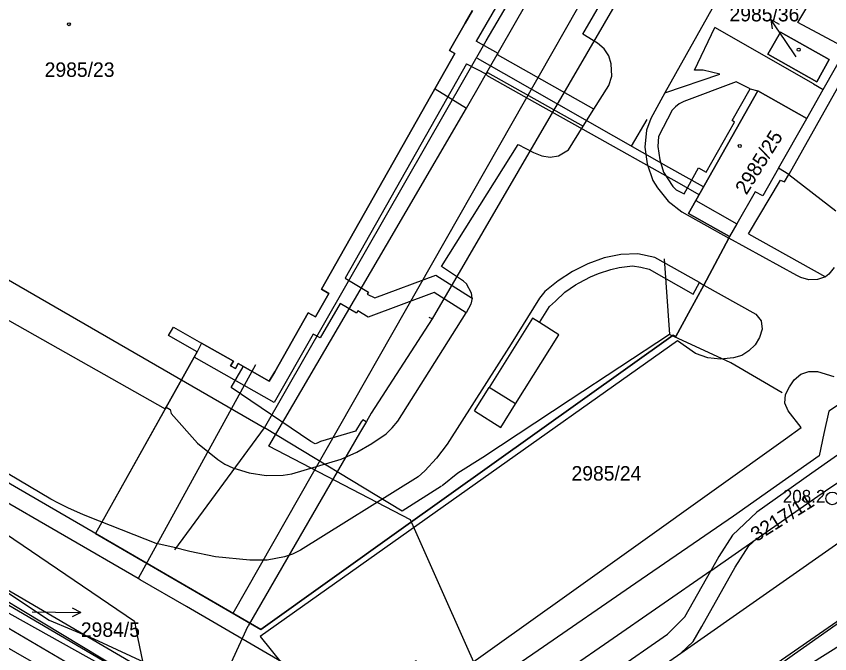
# Model space of a CAD drawing. Extents: x -620475 to -619963, y -1123010 to -1122510.
# Drawn here: x -620108.2 to -620012.5, y -1122830.6 to -1122755.5 of the extents above; entities that cross this region are included whole.
import ezdxf

# ---------------------------------------------------------------- set-up
doc = ezdxf.new("R2010")
doc.units = 0
for name, color, linetype in [('CETIN', 7, 'Continuous'), ('GasNet', 7, 'Continuous'), ('Hranice parcel', 7, 'Continuous'), ('Parcelní čísla', 7, 'Continuous'), ('Pop  PČ popisy', 7, 'Continuous'), ('VAS stoka', 7, 'Continuous'), ('VAS vodovod', 7, 'Continuous'), ('Vnitřní kresba', 7, 'Continuous'), ('Věcná břemena k části', 7, 'Continuous'), ('Značky bodu BP', 7, 'Continuous'), ('Značky budov', 7, 'Continuous')]:
    doc.layers.add(name, color=color, linetype=linetype)

msp = doc.modelspace()

# ---------------------------------------------------------------- linework, layer by layer
at = {"layer": 'CETIN'}
for points in [[(-620322.39, -1122622.262), (-620301.06, -1122636.75), (-620273.539, -1122652.218), (-620253.246, -1122663.163), (-620204.022, -1122698.845), (-620159.643, -1122769.192), (-620144.669, -1122791.286), (-620140.333, -1122798.335), (-620134.98, -1122805.248), (-620121.226, -1122817.175), (-620095.953, -1122832.424), (-620068.004, -1122848.181)], [(-620164.261, -1122757.63), (-620162.95, -1122761.03), (-620156.11, -1122769.9), (-620136.563, -1122796.46), (-620117.888, -1122817.631), (-620104.34, -1122826.6), (-620099.09, -1122828.81), (-620092.09, -1122832.08), (-620086.33, -1122833.54), (-620081.024, -1122834.312)]]:
    msp.add_lwpolyline(points, dxfattribs=at)
at = {"layer": 'GasNet'}
for points in [[(-620046.14, -1122851.29), (-620053.62, -1122841.38), (-620061.16, -1122831.41), (-620068.48, -1122836.5), (-620088.2, -1122824.99), (-620093.656, -1122821.845), (-620093.89, -1122821.71), (-620111.26, -1122811.68), (-620133.38, -1122798.37), (-620145.72, -1122781.6), (-620162.54, -1122758.52), (-620166.304, -1122761.04), (-620166.886, -1122761.429), (-620167.468, -1122761.818), (-620169.13, -1122762.93), (-620169.189, -1122762.97)], [(-620080.07, -1122796.57), (-620093.89, -1122821.71)], [(-619978.453, -1122804.325), (-619997.91, -1122817.46), (-620001.69, -1122820.05), (-620016.67, -1122830.62), (-620025.79, -1122837.14), (-620030.05, -1122839.94), (-620046.14, -1122851.29)]]:
    msp.add_lwpolyline(points, dxfattribs=at)
at = {"layer": 'Hranice parcel'}
for p, q in [((-620018.54, -1122773.42), (-620015.21, -1122767.58)), ((-620026.52, -1122820.79), (-620021.18, -1122817.07))]:
    msp.add_line(p, q, dxfattribs=at)
for points in [[(-620027.34, -1122787.19), (-620029.12, -1122790.47), (-620030.63, -1122793.23), (-620030.93, -1122793.08), (-620062.93, -1122815.9), (-620079.47, -1122827.69), (-620107.97, -1122811.15), (-620126.88, -1122800.18), (-620134.93, -1122794.41), (-620148.77, -1122775.1), (-620158.3, -1122761.8), (-620160.13, -1122754.62), (-620158.82, -1122744.94), (-620155.87, -1122738.11), (-620144.37, -1122714.62)], [(-620004.122, -1122750.583), (-620017.33, -1122774.17), (-620018.54, -1122773.42)], [(-620015.21, -1122767.58), (-620013.28, -1122764.14), (-620010.56, -1122759.32), (-620016.25, -1122756.27), (-620012.77, -1122750.41)], [(-620122.58, -1122783.75), (-620090.7, -1122801.75), (-620090.59, -1122801.55), (-620087.3, -1122795.66), (-620086.96, -1122795.04), (-620090.3, -1122793.12), (-620089.73, -1122792.12), (-620086.43, -1122793.99), (-620082.68, -1122796.11), (-620083.01, -1122796.68), (-620082.45, -1122797), (-620082.12, -1122796.42), (-620078.46, -1122798.5), (-620077.82, -1122797.38), (-620073.87, -1122790.42), (-620073.02, -1122790.9), (-620071.46, -1122788.15), (-620072.31, -1122787.67), (-620056.64, -1122759.92), (-620057.24, -1122759.58), (-620055.41, -1122756.34), (-620054.56, -1122754.84)], [(-620019.78, -1122760.01), (-620014.04, -1122763.25), (-620012.58, -1122760.64), (-620018.31, -1122757.41), (-620019.78, -1122760.01)], [(-620072.47, -1122846.25), (-620119.48, -1122820.03), (-620130.17, -1122810.08), (-620136, -1122804.68), (-620136.79, -1122803.52), (-620163.81, -1122763.48)], [(-620069.79, -1122845.77), (-620093.24, -1122832.45), (-620114.36, -1122820.1), (-620123.37, -1122813.77), (-620129.15, -1122808.98), (-620134.98, -1122803.58), (-620147.22, -1122786.5), (-620163.81, -1122763.48)], [(-620015.21, -1122767.58), (-620020.97, -1122764.3), (-620028.26, -1122777.23), (-620029.12, -1122778.75), (-620024.29, -1122781.46)], [(-620074.02, -1122848.16), (-620095.17, -1122835.78), (-620116.57, -1122823.25), (-620125.58, -1122816.92), (-620133.3, -1122810.53), (-620139.43, -1122803.84), (-620150.35, -1122788.75), (-620165.02, -1122768.39), (-620166.09, -1122767.67), (-620166.7, -1122767.69)], [(-620018.54, -1122773.42), (-620020.4, -1122776.68), (-620021.28, -1122776.18), (-620023.43, -1122779.95), (-620024.29, -1122781.46)], [(-620024.29, -1122781.46), (-620024.38, -1122781.64), (-620027.34, -1122787.19)], [(-620027.34, -1122787.19), (-620021.21, -1122790.6), (-620020.57, -1122791.37), (-620020.47, -1122792.38), (-620020.76, -1122793.34), (-620021.28, -1122794.22), (-620022.02, -1122794.92), (-620022.87, -1122795.46), (-620023.84, -1122795.75), (-620024.96, -1122795.87), (-620025.37, -1122795.91), (-620026.87, -1122795.75), (-620028.3, -1122795.22), (-620030.44, -1122793.73), (-620056.1, -1122811.95), (-620079.53, -1122828.52), (-620068.86, -1122841.8), (-620043.43, -1122823.66), (-620017.73, -1122805.26), (-620015.89, -1122803.95), (-620017.39, -1122801.99), (-620017.8, -1122801.06), (-620017.7, -1122800.06), (-620017.25, -1122799.14), (-620016.69, -1122798.31), (-620015.92, -1122797.65), (-620014.98, -1122797.35), (-620013.97, -1122797.33), (-620012.05, -1122797.95)], [(-619977.351, -1122803.065), (-619989.26, -1122811.36), (-619995.85, -1122815.89), (-620011.68, -1122826.8), (-620019.22, -1122832.01), (-620044.54, -1122849.47), (-620064.79, -1122863.44), (-620079.86, -1122873.87), (-620081.95, -1122879.05), (-620081.71, -1122879.39)], [(-620007.52, -1122804.34), (-620014.61, -1122809.32), (-620021.11, -1122813.89), (-620023.96, -1122816.62), (-620025.58, -1122819.12), (-620026.52, -1122820.79)], [(-620021.18, -1122817.07), (-620013.01, -1122811.39), (-620007.39, -1122807.62), (-620007.17, -1122807.47)], [(-620074.02, -1122848.16), (-620069.41, -1122850.86), (-620061.9, -1122850.43), (-620053.99, -1122846.97), (-620049.77, -1122844.23), (-620030.04, -1122830.5), (-620028.57, -1122829.11), (-620027.57, -1122827.35), (-620023.65, -1122820.37), (-620022.03, -1122817.87), (-620021.18, -1122817.07)], [(-620026.52, -1122820.79), (-620038.5, -1122829.12), (-620047.37, -1122835.25), (-620060.13, -1122844.05), (-620068.97, -1122845.62), (-620069.79, -1122845.77)]]:
    msp.add_lwpolyline(points, dxfattribs=at)
at = {"layer": 'Pop  PČ popisy'}
for p, q in [((-620017.77, -1122758.39), (-620019.448, -1122755.902)), ((-620019.448, -1122755.902), (-620018.473, -1122756.452)), ((-620019.448, -1122755.902), (-620019.303, -1122757.012)), ((-620016.47, -1122760.3), (-620017.77, -1122758.39)), ((-620106.35, -1122825.61), (-620103.63, -1122825.67)), ((-620103.63, -1122825.67), (-620100.629, -1122825.722)), ((-620100.629, -1122825.722), (-620101.64, -1122826.206)), ((-620100.629, -1122825.722), (-620101.622, -1122825.204))]:
    msp.add_line(p, q, dxfattribs=at)
at = {"layer": 'VAS stoka'}
for p, q in [((-620052.94, -1122758.439), (-620033.543, -1122724.847)), ((-620079.029, -1122803.959), (-620052.94, -1122758.439)), ((-620031.44, -1122773.35), (-620053.969, -1122760.492)), ((-620034.04, -1122767.68), (-620035.863, -1122770.826)), ((-620027.385, -1122775.627), (-620031.44, -1122773.35)), ((-620122.365, -1122778.921), (-620079.029, -1122803.959)), ((-620031.979, -1122784.069), (-620031.366, -1122792.974)), ((-620024.169, -1122796.309), (-620031.366, -1122792.974)), ((-620018.119, -1122799.839), (-620024.169, -1122796.309)), ((-620089.569, -1122818.32), (-620079.029, -1122803.959)), ((-620062.84, -1122813.779), (-620079.029, -1122803.959)), ((-620061.86, -1122814.789), (-620078.5, -1122806.14)), ((-620053.33, -1122807.479), (-620056.28, -1122809.32)), ((-620056.28, -1122809.32), (-620058.12, -1122810.81)), ((-620058.19, -1122810.85), (-620062.82, -1122813.8))]:
    msp.add_line(p, q, dxfattribs=at)
for points in [[(-620055.26, -1122766.37), (-620053.564, -1122763.408), (-620052.846, -1122762.154), (-620032.173, -1122726.045)], [(-620027.895, -1122776.551), (-620030.2, -1122775.22), (-620041.535, -1122768.859), (-620047.202, -1122765.678), (-620052.869, -1122762.498)], [(-620058.939, -1122764.072), (-620057.1, -1122765.221), (-620055.26, -1122766.37)], [(-620078.5, -1122806.14), (-620064.682, -1122782.494), (-620062.355, -1122778.511), (-620055.26, -1122766.37)], [(-620031.366, -1122792.974), (-620043.054, -1122800.691), (-620053.33, -1122807.479)], [(-620051.68, -1122837.63), (-620057.913, -1122823.646), (-620061.86, -1122814.789)], [(-619997.17, -1122820.747), (-619998.311, -1122821.463), (-620010.725, -1122829.248), (-620019.05, -1122834.47)]]:
    msp.add_lwpolyline(points, dxfattribs=at)
at = {"layer": 'VAS vodovod'}
msp.add_line((-620059.31, -1122791.147), (-620059.64, -1122790.99), dxfattribs=at)
for points in [[(-620028.042, -1122729.66), (-620082.75, -1122825.82)], [(-620025.037, -1122732.288), (-620059.31, -1122791.147), (-620066.473, -1122802.261), (-620067.023, -1122803.23), (-620067.856, -1122804.615), (-620080.94, -1122827.26)], [(-620094.32, -1122826.78), (-620136.84, -1122797.89), (-620162.059, -1122762.891), (-620162.19, -1122762.71)], [(-619974.711, -1122776.311), (-619980.2, -1122780.38), (-619982.016, -1122781.485), (-619983.728, -1122782.528), (-619988.19, -1122785.414), (-619992.55, -1122788.237), (-619997.475, -1122791.487), (-620002.4, -1122794.737), (-620006.714, -1122797.839), (-620011.04, -1122800.95), (-620011.83, -1122801.485), (-620012.62, -1122802.02), (-620013.195, -1122804.65), (-620013.769, -1122807.28), (-620018.794, -1122810.815), (-620023.82, -1122814.35), (-620035.32, -1122822.27), (-620046.82, -1122830.19), (-620050.815, -1122832.916), (-620054.81, -1122835.641), (-620056.561, -1122836.89), (-620058.311, -1122838.14), (-620058.561, -1122838.3), (-620058.81, -1122838.46)], [(-620067.049, -1122803.272), (-620067.433, -1122803.035), (-620067.645, -1122803.278), (-620068.306, -1122804.373), (-620072.429, -1122805.571), (-620072.825, -1122805.796), (-620073.063, -1122805.844), (-620073.57, -1122805.563), (-620082.951, -1122799.213), (-620081.541, -1122796.814)], [(-620094.32, -1122826.78), (-620093.93, -1122828.821), (-620093.379, -1122831.42), (-620088.087, -1122834.265), (-620082.794, -1122837.11), (-620081.868, -1122837.671), (-620081.6, -1122837.833), (-620080.012, -1122838.796), (-620077.229, -1122840.481), (-620076.346, -1122840.575), (-620075.462, -1122840.668), (-620072.956, -1122842.224), (-620070.45, -1122843.781), (-620068.395, -1122843.54), (-620066.34, -1122843.3), (-620062.75, -1122841.311), (-620059.159, -1122839.32), (-620057.681, -1122841.329), (-620056.202, -1122843.338), (-620052.72, -1122848.556), (-620049.46, -1122853.441), (-620049.285, -1122853.763), (-620049.11, -1122854.085)], [(-620076.288, -1122839.551), (-620076.846, -1122839.2), (-620078.302, -1122838.25), (-620079.757, -1122837.3), (-620080.598, -1122836.752), (-620081.328, -1122836.275), (-620082.669, -1122835.4), (-620082.905, -1122833.74), (-620083.14, -1122832.08), (-620082.04, -1122829.671), (-620080.94, -1122827.26)]]:
    msp.add_lwpolyline(points, dxfattribs=at)
at = {"layer": 'Vnitřní kresba'}
for p, q in [((-620035.9, -1122726.57), (-620054.1, -1122758.47)), ((-620041.55, -1122757.64), (-620033.04, -1122742.83)), ((-620022.92, -1122748.42), (-620031.91, -1122764.55)), ((-620028.43, -1122761.89), (-620026.05, -1122756.86)), ((-620014.44, -1122763.48), (-620026.05, -1122756.86)), ((-620039.84, -1122758.71), (-620041.55, -1122757.64)), ((-620051.51, -1122759.9), (-620054.1, -1122758.47)), ((-620039.07, -1122759.38), (-620039.84, -1122758.71)), ((-620051.62, -1122760.07), (-620051.51, -1122759.9)), ((-620038.52, -1122760.2), (-620039.07, -1122759.38)), ((-620040.26, -1122766.46), (-620051.62, -1122760.07)), ((-620038.22, -1122761.15), (-620038.52, -1122760.2)), ((-620055.24, -1122761.12), (-620069.55, -1122786.35)), ((-620055.24, -1122761.12), (-620052.9, -1122762.36)), ((-620038.17, -1122762.58), (-620038.22, -1122761.15)), ((-620052.9, -1122762.36), (-620052.8, -1122762.16)), ((-620052.8, -1122762.16), (-620041.52, -1122768.46)), ((-620038.52, -1122763.67), (-620038.17, -1122762.58)), ((-620031.91, -1122764.55), (-620025.43, -1122762.36)), ((-620027.41, -1122761.88), (-620028.43, -1122761.89)), ((-620025.43, -1122762.36), (-620027.41, -1122761.88)), ((-620040.26, -1122766.46), (-620038.52, -1122763.67)), ((-620023.51, -1122763.25), (-620029.67, -1122765.56)), ((-620021.87, -1122764.08), (-620023.51, -1122763.25)), ((-620014.44, -1122763.48), (-620013.28, -1122764.14)), ((-620031.91, -1122764.55), (-620033.55, -1122767.57)), ((-620024.01, -1122767.82), (-620021.87, -1122764.08)), ((-620021.87, -1122764.08), (-620020.97, -1122764.3)), ((-620029.67, -1122765.56), (-620030.22, -1122765.84)), ((-620041.52, -1122768.46), (-620040.26, -1122766.46)), ((-620031.05, -1122766.59), (-620032.68, -1122769.69)), ((-620030.66, -1122766.18), (-620031.05, -1122766.59)), ((-620030.22, -1122765.84), (-620030.66, -1122766.18)), ((-620033.55, -1122767.57), (-620034.07, -1122768.94)), ((-620043.24, -1122771.24), (-620041.52, -1122768.46)), ((-620027.07, -1122773.88), (-620023.72, -1122768.01)), ((-620023.72, -1122768.01), (-620024.01, -1122767.82)), ((-620034.07, -1122768.94), (-620034.29, -1122770.95)), ((-620032.68, -1122769.69), (-620032.73, -1122770.86)), ((-620058.21, -1122785), (-620049.19, -1122770.62)), ((-620049.19, -1122770.62), (-620047.36, -1122771.58)), ((-620044.41, -1122771.98), (-620043.24, -1122771.24)), ((-620034.29, -1122770.95), (-620033.98, -1122772.91)), ((-620032.73, -1122770.86), (-620032.52, -1122772.45)), ((-620047.36, -1122771.58), (-620046.4, -1122771.95)), ((-620046.4, -1122771.95), (-620045.42, -1122772.1)), ((-620045.42, -1122772.1), (-620044.41, -1122771.98)), ((-620033.98, -1122772.91), (-620033.32, -1122774.85)), ((-620032.52, -1122772.45), (-620032.06, -1122773.89)), ((-620032.06, -1122773.89), (-620030.97, -1122775.57)), ((-620029.65, -1122776.45), (-620027.94, -1122773.37)), ((-620027.94, -1122773.37), (-620027.07, -1122773.88)), ((-620017.82, -1122775.04), (-620017.33, -1122774.17)), ((-620017.33, -1122774.17), (-620011.79, -1122778.42)), ((-620033.32, -1122774.85), (-620032.78, -1122775.71)), ((-620022.06, -1122781.16), (-620018.29, -1122774.82)), ((-620018.29, -1122774.82), (-620017.82, -1122775.04)), ((-620032.78, -1122775.71), (-620031.51, -1122777.29)), ((-620030.97, -1122775.57), (-620030.6, -1122775.96)), ((-620030.6, -1122775.96), (-620029.65, -1122776.45)), ((-620031.51, -1122777.29), (-620029.92, -1122778.54)), ((-620028.26, -1122777.23), (-620023.43, -1122779.95)), ((-620029.92, -1122778.54), (-620024.38, -1122781.64)), ((-620016.38, -1122786.03), (-620024.38, -1122781.64)), ((-620022.06, -1122781.16), (-620013.03, -1122786.2)), ((-620037.11, -1122783.56), (-620039.07, -1122783.97)), ((-620035.08, -1122783.5), (-620037.11, -1122783.56)), ((-620033.11, -1122783.92), (-620035.08, -1122783.5)), ((-620040.98, -1122784.66), (-620042.78, -1122785.58)), ((-620039.07, -1122783.97), (-620040.98, -1122784.66)), ((-620027.85, -1122786.88), (-620033.11, -1122783.92)), ((-620055.6, -1122786.71), (-620058.21, -1122785)), ((-620042.78, -1122785.58), (-620044.47, -1122786.69)), ((-620039.72, -1122785.82), (-620038.28, -1122785.33)), ((-620038.28, -1122785.33), (-620037.29, -1122785.12)), ((-620037.29, -1122785.12), (-620035.74, -1122784.92)), ((-620035.74, -1122784.92), (-620034.76, -1122785.06)), ((-620034.76, -1122785.06), (-620033.77, -1122785.31)), ((-620033.77, -1122785.31), (-620028.59, -1122788.23)), ((-620011.99, -1122785.12), (-620012.63, -1122785.89)), ((-620069.55, -1122786.35), (-620066.78, -1122787.99)), ((-620066.03, -1122788.67), (-620058.85, -1122786.02)), ((-620058.85, -1122786.02), (-620054.57, -1122788.73)), ((-620055.26, -1122787.03), (-620055.6, -1122786.71)), ((-620044.47, -1122786.69), (-620046.04, -1122787.93)), ((-620041.98, -1122786.91), (-620040.65, -1122786.19)), ((-620040.65, -1122786.19), (-620039.72, -1122785.82)), ((-620015.91, -1122786.27), (-620016.38, -1122786.03)), ((-620014.97, -1122786.55), (-620015.91, -1122786.27)), ((-620013.96, -1122786.51), (-620014.97, -1122786.55)), ((-620013.03, -1122786.2), (-620013.96, -1122786.51)), ((-620012.63, -1122785.89), (-620013.03, -1122786.2)), ((-620054.65, -1122788.11), (-620055.26, -1122787.03)), ((-620043.69, -1122788), (-620042.42, -1122787.14)), ((-620042.42, -1122787.14), (-620041.98, -1122786.91)), ((-620028.59, -1122788.23), (-620027.85, -1122786.88)), ((-620027.85, -1122786.88), (-620027.34, -1122787.19)), ((-620066.78, -1122787.99), (-620066.95, -1122788.23)), ((-620066.95, -1122788.23), (-620066.03, -1122788.67)), ((-620059.07, -1122788.06), (-620066.82, -1122790.95)), ((-620055.29, -1122790.43), (-620059.07, -1122788.06)), ((-620054.57, -1122788.73), (-620054.65, -1122788.11)), ((-620046.04, -1122787.93), (-620046.66, -1122788.71)), ((-620044.78, -1122789.08), (-620043.69, -1122788)), ((-620070.13, -1122789.33), (-620072.48, -1122793.37)), ((-620068.2, -1122790.46), (-620070.13, -1122789.33)), ((-620054.73, -1122789.43), (-620055.29, -1122790.43)), ((-620054.57, -1122788.73), (-620054.73, -1122789.43)), ((-620046.66, -1122788.71), (-620050.01, -1122794.09)), ((-620045.49, -1122789.69), (-620044.78, -1122789.08)), ((-620068.05, -1122790.2), (-620068.2, -1122790.46)), ((-620066.82, -1122790.95), (-620068.05, -1122790.2)), ((-620063.35, -1122803.17), (-620055.29, -1122790.43)), ((-620046.67, -1122791.59), (-620045.49, -1122789.69)), ((-620044.39, -1122793.03), (-620046.67, -1122791.59)), ((-620073.28, -1122792.94), (-620077.88, -1122800.99)), ((-620072.48, -1122793.37), (-620073.28, -1122792.94)), ((-620049.47, -1122801.15), (-620044.39, -1122793.03)), ((-620050.01, -1122794.09), (-620057.54, -1122805.91)), ((-620077.88, -1122800.99), (-620087.3, -1122795.66)), ((-620054.32, -1122801.97), (-620052.58, -1122799.22)), ((-620049.47, -1122801.15), (-620052.58, -1122799.22)), ((-620104.17, -1122812.35), (-620119.93, -1122803.03)), ((-620064.71, -1122804.67), (-620064, -1122803.96)), ((-620064, -1122803.96), (-620063.35, -1122803.17)), ((-620066.39, -1122805.81), (-620064.71, -1122804.67)), ((-620086.89, -1122805.77), (-620084.53, -1122807.72)), ((-620068.14, -1122806.82), (-620066.39, -1122805.81)), ((-620069.99, -1122807.67), (-620068.14, -1122806.82)), ((-620057.54, -1122805.91), (-620058.79, -1122807.53)), ((-620084.53, -1122807.72), (-620083.69, -1122808.26)), ((-620075.82, -1122809.38), (-620069.99, -1122807.67)), ((-620058.79, -1122807.53), (-620060.14, -1122809.05)), ((-620083.69, -1122808.26), (-620082.76, -1122808.7)), ((-620082.76, -1122808.7), (-620080.83, -1122809.28)), ((-620080.83, -1122809.28), (-620078.84, -1122809.59)), ((-620078.84, -1122809.59), (-620076.83, -1122809.56)), ((-620076.83, -1122809.56), (-620075.82, -1122809.38)), ((-620060.14, -1122809.05), (-620060.93, -1122809.75)), ((-620030.04, -1122830.5), (-620000, -1122809.41)), ((-620060.93, -1122809.75), (-620074.77, -1122818.38)), ((-620103.27, -1122812.85), (-620104.17, -1122812.35)), ((-620102.16, -1122813.38), (-620103.27, -1122812.85)), ((-620100.32, -1122814.22), (-620102.16, -1122813.38)), ((-620098.43, -1122814.97), (-620100.32, -1122814.22)), ((-620091.75, -1122817.59), (-620098.43, -1122814.97)), ((-620089.79, -1122818.03), (-620091.75, -1122817.59)), ((-620087.81, -1122818.54), (-620089.79, -1122818.03)), ((-620127.92, -1122819.29), (-620075.39, -1122849.03)), ((-620084.78, -1122819.14), (-620087.81, -1122818.54)), ((-620080.74, -1122819.56), (-620084.78, -1122819.14)), ((-620076.68, -1122819.17), (-620078.69, -1122819.55)), ((-620075.71, -1122818.84), (-620076.68, -1122819.17)), ((-620074.77, -1122818.38), (-620075.71, -1122818.84)), ((-620078.69, -1122819.55), (-620080.74, -1122819.56)), ((-620029.57, -1122826.21), (-620026.52, -1122820.79)), ((-620093.98, -1122833.75), (-620115.22, -1122821.33)), ((-620030.46, -1122827.11), (-620029.57, -1122826.21)), ((-620031.61, -1122828.24), (-620030.46, -1122827.11)), ((-620051.34, -1122841.97), (-620031.61, -1122828.24))]:
    msp.add_line(p, q, dxfattribs=at)
for points in [[(-620046.67, -1122791.59), (-620047.49, -1122791.07), (-620052.58, -1122799.22)], [(-620090.59, -1122801.55), (-620090.11, -1122801.83), (-620089.99, -1122802.28), (-620086.89, -1122805.77)], [(-620054.32, -1122801.97), (-620051.2, -1122803.92), (-620049.47, -1122801.15)]]:
    msp.add_lwpolyline(points, dxfattribs=at)
at = {"layer": 'Věcná břemena k části'}
for points in [[(-620054.56, -1122754.84), (-620055.41, -1122756.34), (-620057.24, -1122759.58), (-620056.64, -1122759.92), (-620072.31, -1122787.67), (-620071.46, -1122788.15), (-620073.02, -1122790.9), (-620073.87, -1122790.42), (-620077.82, -1122797.38), (-620078.46, -1122798.5), (-620082.12, -1122796.42), (-620082.45, -1122797), (-620083.01, -1122796.68), (-620082.68, -1122796.11), (-620086.43, -1122793.99), (-620086.96, -1122795.04), (-620087.3, -1122795.66), (-620090.59, -1122801.55), (-620090.7, -1122801.75), (-620098.89, -1122816.42), (-620079.47, -1122827.69), (-620062.93, -1122815.9), (-620030.93, -1122793.08), (-620030.63, -1122793.23), (-620029.12, -1122790.47), (-620027.34, -1122787.19), (-620024.38, -1122781.64), (-620024.29, -1122781.46), (-620029.12, -1122778.75), (-620028.26, -1122777.23), (-620020.97, -1122764.3), (-620015.21, -1122767.58), (-620013.28, -1122764.14), (-620010.56, -1122759.32), (-620016.25, -1122756.27), (-620012.77, -1122750.41)], [(-620054.56, -1122754.84), (-620055.41, -1122756.34), (-620057.24, -1122759.58), (-620056.64, -1122759.92), (-620072.31, -1122787.67), (-620071.46, -1122788.15), (-620073.02, -1122790.9), (-620073.87, -1122790.42), (-620077.82, -1122797.38), (-620078.46, -1122798.5), (-620082.12, -1122796.42), (-620082.45, -1122797), (-620083.01, -1122796.68), (-620082.68, -1122796.11), (-620086.43, -1122793.99), (-620086.96, -1122795.04), (-620087.3, -1122795.66), (-620098.89, -1122816.42), (-620079.47, -1122827.69), (-620062.93, -1122815.9), (-620030.93, -1122793.08), (-620030.63, -1122793.23), (-620029.12, -1122790.47), (-620027.34, -1122787.19), (-620024.38, -1122781.64), (-620024.29, -1122781.46), (-620029.12, -1122778.75), (-620028.26, -1122777.23), (-620020.97, -1122764.3), (-620015.21, -1122767.58), (-620013.28, -1122764.14), (-620010.56, -1122759.32), (-620016.25, -1122756.27), (-620012.77, -1122750.41)], [(-620054.56, -1122754.84), (-620055.41, -1122756.34), (-620057.24, -1122759.58), (-620056.64, -1122759.92), (-620072.31, -1122787.67), (-620071.46, -1122788.15), (-620073.02, -1122790.9), (-620073.87, -1122790.42), (-620077.82, -1122797.38), (-620078.46, -1122798.5), (-620082.12, -1122796.42), (-620082.45, -1122797), (-620083.01, -1122796.68), (-620082.68, -1122796.11), (-620086.43, -1122793.99), (-620086.96, -1122795.04), (-620087.3, -1122795.66), (-620090.59, -1122801.55), (-620090.7, -1122801.75), (-620098.89, -1122816.42), (-620079.47, -1122827.69), (-620062.93, -1122815.9), (-620030.93, -1122793.08), (-620030.63, -1122793.23), (-620027.34, -1122787.19), (-620024.38, -1122781.64), (-620024.29, -1122781.46), (-620029.12, -1122778.75), (-620028.26, -1122777.23), (-620020.97, -1122764.3), (-620015.21, -1122767.58), (-620013.28, -1122764.14), (-620010.56, -1122759.32), (-620016.25, -1122756.27), (-620012.77, -1122750.41)], [(-620054.56, -1122754.84), (-620055.41, -1122756.34), (-620057.24, -1122759.58), (-620056.64, -1122759.92), (-620072.31, -1122787.67), (-620071.46, -1122788.15), (-620073.02, -1122790.9), (-620073.87, -1122790.42), (-620077.82, -1122797.38), (-620078.46, -1122798.5), (-620082.12, -1122796.42), (-620082.45, -1122797), (-620083.01, -1122796.68), (-620082.68, -1122796.11), (-620086.43, -1122793.99), (-620086.96, -1122795.04), (-620087.3, -1122795.66), (-620090.59, -1122801.55), (-620090.7, -1122801.75), (-620098.89, -1122816.42), (-620079.47, -1122827.69), (-620062.93, -1122815.9), (-620030.93, -1122793.08), (-620030.63, -1122793.23), (-620029.12, -1122790.47), (-620027.34, -1122787.19), (-620024.38, -1122781.64), (-620024.29, -1122781.46), (-620029.12, -1122778.75), (-620028.26, -1122777.23), (-620020.97, -1122764.3), (-620015.21, -1122767.58), (-620013.28, -1122764.14), (-620010.56, -1122759.32), (-620016.25, -1122756.27), (-620012.77, -1122750.41)], [(-620018.31, -1122757.41), (-620012.58, -1122760.64), (-620014.04, -1122763.25), (-620019.78, -1122760.01), (-620018.31, -1122757.41)], [(-620012.58, -1122760.64), (-620014.04, -1122763.25), (-620019.78, -1122760.01), (-620018.31, -1122757.41), (-620012.58, -1122760.64)], [(-620012.58, -1122760.64), (-620014.04, -1122763.25), (-620019.78, -1122760.01), (-620018.31, -1122757.41), (-620012.58, -1122760.64)], [(-620012.58, -1122760.64), (-620014.04, -1122763.25), (-620019.78, -1122760.01), (-620018.31, -1122757.41), (-620012.58, -1122760.64)]]:
    msp.add_lwpolyline(points, dxfattribs=at)
at = {"layer": 'Značky bodu BP'}
msp.add_circle((-620012.22, -1122812.28), 0.75, dxfattribs=at)
at = {"layer": 'Značky budov'}
for centre in [(-620102.037, -1122756.469), (-620016.167, -1122759.469), (-620023.097, -1122770.799)]:
    msp.add_circle(centre, 0.175, dxfattribs=at)

# ---------------------------------------------------------------- texts
at = {"layer": 'Parcelní čísla'}
for s, p in [('2985/36', (-620024.308, -1122756.14)), ('2985/23', (-620104.888, -1122762.666)), ('2985/24', (-620042.9, -1122810.18)), ('2984/5', (-620100.63, -1122828.573))]:
    msp.add_text(s, height=1.7, dxfattribs=at).set_placement(p)
for s, rotation, p in [('2985/25', 58, (-620022.312, -1122776.645)), ('3217/11', 32, (-620021.149, -1122817.43))]:
    msp.add_text(s, height=1.7, rotation=rotation, dxfattribs=at).set_placement(p)
at = {"layer": 'Značky bodu BP'}
msp.add_text('208.2', height=1.5, dxfattribs=at).set_placement((-620018.04, -1122812.78))

doc.saveas('drawing.dxf')
